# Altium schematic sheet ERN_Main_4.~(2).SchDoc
size A; SheetNumber: 4; SheetTotal: 4
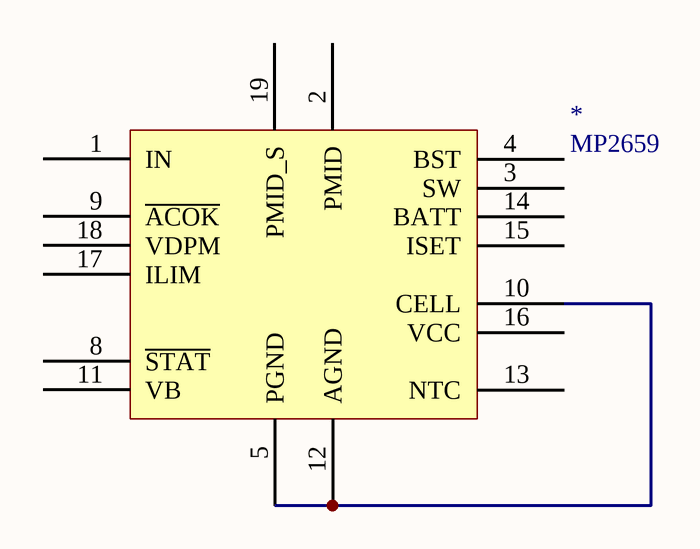
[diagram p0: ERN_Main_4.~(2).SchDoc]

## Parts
*  MP2659

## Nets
Net*_5: *.5(PGND) *.10(CELL) *.12(AGND)

Not connected (* = marked no-connect by the designer): * 1(IN) 2(PMID) 3(SW) 4(BST) 8(~{STAT}) 9(~{ACOK}) 11(VB) 13(NTC) 14(BATT) 15(ISET) 16(VCC) 17(ILIM) 18(VDPM) 19(PMID_S)

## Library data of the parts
* = MP2659: 3S-6S Standalone Switching Charger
